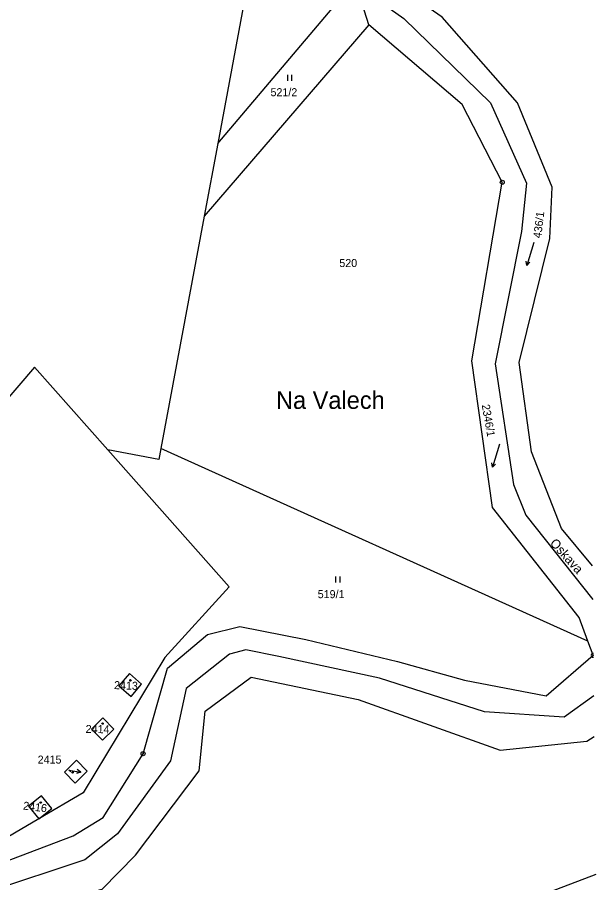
# Model space of a CAD drawing. Extents: x -555757 to -553364, y -1100723 to -1096439.
# Drawn here: x -553764.6 to -553620.1, y -1099734.7 to -1099518.5 of the extents above; entities that cross this region are included whole.
import ezdxf

# ---------------------------------------------------------------- set-up
doc = ezdxf.new("R2010")
doc.units = 0
for name, color, linetype in [('00_NÁVRH - 0.35 mm', 7, 'Continuous'), ('BUDOVY', 7, 'Continuous'), ('C$SLO$PARCELY', 7, 'Continuous'), ('HRANICE$PARCELY', 7, 'Continuous'), ('HRANICE_PARCEL', 7, 'Continuous'), ('PLOTY', 7, 'Continuous'), ('SLOUPY', 7, 'Continuous'), ('VSTUP', 7, 'Continuous'), ('ZNA$KY$KULTUR', 7, 'Continuous')]:
    doc.layers.add(name, color=color, linetype=linetype)

# ---------------------------------------------------------------- blocks, each defined once
blk = doc.blocks.new('8$02')
at = {"layer": 'ZNA$KY$KULTUR'}
for p, q in [((0.864, 2.855), (-0.89, -2.882)), ((-0.89, -2.882), (-1.083, -1.802)), ((-0.89, -2.882), (-0.125, -2.095))]:
    blk.add_line(p, q, dxfattribs=at)
blk = doc.blocks.new('4$02')
at = {"layer": 'SLOUPY'}
blk.add_circle((0, 0), 0.175, dxfattribs=at)
blk = doc.blocks.new('1029')
at = {"layer": 'PLOTY'}
for p, q in [((0, 0), (2.964, -0.468)), ((2.964, -0.468), (2.052, 0.182)), ((2.964, -0.468), (1.897, -0.807))]:
    blk.add_line(p, q, dxfattribs=at)
blk = doc.blocks.new('3$06')
at = {"layer": 'SLOUPY'}
for p, q in [((-0.517, 0.235), (-0.517, 1.735)), ((0.517, 0.235), (0.517, 1.735))]:
    blk.add_line(p, q, dxfattribs=at)
blk = doc.blocks.new('1$05')
at = {"layer": 'SLOUPY'}
for radius in [0.5, 0.032]:
    blk.add_circle((0, 0), radius, dxfattribs=at)

msp = doc.modelspace()

# ---------------------------------------------------------------- linework, layer by layer
at = {"layer": '00_NÁVRH - 0.35 mm'}
msp.add_open_spline([(-553819.59, -1099648.16), (-553819.4, -1099646.98), (-553818.56, -1099642.68), (-553816.68, -1099632.95), (-553812.02, -1099604.96), (-553809.79, -1099592.42), (-553806.53, -1099573.82), (-553806.2, -1099571.41), (-553804.77, -1099565.39), (-553798.08, -1099537.61), (-553796.19, -1099528.87), (-553794.16, -1099518.96), (-553793.97, -1099518.03), (-553793.87, -1099517.09), (-553793.75, -1099515.21), (-553792.36, -1099501.3), (-553791.83, -1099495.69), (-553791.31, -1099490.99), (-553790.46, -1099486.24), (-553789.17, -1099479.65), (-553786.51, -1099466.71), (-553785.83, -1099463.11), (-553785.36, -1099460.98), (-553785.14, -1099459.44), (-553784.73, -1099457.36), (-553781.96, -1099447.34), (-553777.86, -1099430.86), (-553775.87, -1099421.47), (-553773.63, -1099411.99), (-553771.23, -1099402.7), (-553769.36, -1099395.48), (-553768.64, -1099392.98), (-553768.18, -1099390.94), (-553766.28, -1099385.06), (-553765.16, -1099381.85), (-553762.51, -1099373.89), (-553760.31, -1099367.21), (-553759.89, -1099365.84), (-553759.44, -1099362.93), (-553758.89, -1099359.25), (-553758.81, -1099358.33), (-553758.87, -1099357.66), (-553759.04, -1099356.6), (-553759.19, -1099356.07), (-553760.05, -1099353.69), (-553760.55, -1099352.56), (-553766.32, -1099340.88), (-553766.88, -1099339.66), (-553767.75, -1099337.24), (-553769.45, -1099332.64), (-553770.89, -1099328.75), (-553771.54, -1099327.26), (-553772.2, -1099326.35), (-553775.73, -1099321.61), (-553781.22, -1099315.05), (-553785.27, -1099310.83), (-553785.54, -1099310.54), (-553785.73, -1099310.27), (-553786.37, -1099309.39), (-553819.5, -1099647.57), (-553786.04, -1099309.83)], degree=3, dxfattribs=at)
at = {"layer": 'HRANICE$PARCELY'}
for p, q in [((-553676.74, -1099520.32), (-553680.4, -1099508.77)), ((-553714.51, -1099549.98), (-553683.18, -1099513.03)), ((-553708.15, -1099515.9), (-553714.51, -1099549.98)), ((-553676.74, -1099520.32), (-553717.88, -1099568.1)), ((-553714.51, -1099549.98), (-553717.88, -1099568.1)), ((-553717.88, -1099568.1), (-553728.71, -1099626.16)), ((-553729.22, -1099628.91), (-553741.95, -1099626.54)), ((-553728.71, -1099626.16), (-553729.22, -1099628.91)), ((-553622, -1099674.28), (-553728.71, -1099626.16)), ((-553620.06, -1099732.58), (-553674.71, -1099753.42))]:
    msp.add_line(p, q, dxfattribs=at)
for points in [[(-553620.89, -1099655.48), (-553628.63, -1099646.14), (-553636.12, -1099627.02), (-553639.15, -1099604.73), (-553631.51, -1099573.7), (-553630.95, -1099560.93), (-553639.63, -1099539.86), (-553658.46, -1099518.43), (-553668.42, -1099511.39), (-553668.51, -1099470.76), (-553654.07, -1099454.92), (-553633.67, -1099447), (-553623.15, -1099447.06)], [(-553622, -1099674.28), (-553624.18, -1099668.44), (-553645.83, -1099640.94), (-553650.97, -1099604.28), (-553643.39, -1099559.66), (-553653.45, -1099540.26), (-553676.74, -1099520.32)], [(-553741.95, -1099626.54), (-553760.26, -1099605.89), (-553773.14, -1099620.73)], [(-553741.95, -1099626.54), (-553711.63, -1099660.73), (-553727.7, -1099678.41), (-553748.14, -1099712.19), (-553759.2, -1099718.67), (-553776.11, -1099728.59)], [(-553772.86, -1099731.35), (-553750.62, -1099722.98), (-553743.14, -1099718.36), (-553733.17, -1099702.43), (-553727.09, -1099681.04), (-553717.04, -1099672.62), (-553708.98, -1099670.62), (-553692.52, -1099673.88), (-553669.59, -1099679.36), (-553652.81, -1099684.04), (-553632.42, -1099688), (-553620.66, -1099677.84), (-553622, -1099674.28)], [(-553739.2, -1099685.47), (-553736.14, -1099688.11), (-553733.55, -1099685.03), (-553736.58, -1099682.42), (-553739.2, -1099685.47)], [(-553803.28, -1099822.6), (-553800.12, -1099797.62), (-553791.55, -1099769.92), (-553769.18, -1099743.04), (-553743.39, -1099736.29), (-553735.05, -1099727.74), (-553719.16, -1099706.71), (-553717.63, -1099691.83), (-553706.15, -1099683.31), (-553679.42, -1099688.88), (-553643.93, -1099701.57), (-553622.25, -1099699.32), (-553620.43, -1099698.1)], [(-553746.01, -1099696.28), (-553743.27, -1099699.03), (-553740.46, -1099696.26), (-553743.22, -1099693.49), (-553746.01, -1099696.28)], [(-553749.77, -1099704.03), (-553752.83, -1099707), (-553750.16, -1099709.76), (-553747.12, -1099706.78), (-553749.77, -1099704.03)], [(-553759.2, -1099718.67), (-553755.98, -1099716.12), (-553758.57, -1099712.93), (-553761.76, -1099715.51), (-553759.2, -1099718.67)]]:
    msp.add_lwpolyline(points, dxfattribs=at)
at = {"layer": 'HRANICE_PARCEL'}
for points in [[(-553623.22, -1099440.62), (-553637.4, -1099440.59), (-553654.89, -1099447.65), (-553661.99, -1099453.57), (-553674.34, -1099467.66), (-553675.45, -1099472.16), (-553673.92, -1099502.92), (-553674.7, -1099509.57), (-553672.87, -1099515.35), (-553668, -1099518.73), (-553646.32, -1099539.83), (-553637.37, -1099559.91), (-553638.63, -1099571.96), (-553645.19, -1099605.07), (-553640.58, -1099635.18), (-553637.5, -1099642.82), (-553620.8, -1099663.93)], [(-553623.22, -1099440.62), (-553637.4, -1099440.59), (-553654.89, -1099447.65), (-553661.99, -1099453.57), (-553674.34, -1099467.66), (-553675.45, -1099472.16), (-553673.92, -1099502.92), (-553674.7, -1099509.57), (-553672.87, -1099515.35), (-553668, -1099518.73), (-553646.32, -1099539.83), (-553637.37, -1099559.91), (-553638.63, -1099571.96), (-553645.19, -1099605.07), (-553640.58, -1099635.18), (-553637.5, -1099642.82), (-553620.8, -1099663.93)], [(-553620.54, -1099687.95), (-553627.97, -1099693.34), (-553647.84, -1099691.97), (-553674.12, -1099683.54), (-553699.27, -1099678.15), (-553707.5, -1099676.52), (-553711.54, -1099677.53), (-553722.43, -1099686.1), (-553726.32, -1099704.19), (-553739.54, -1099722.43), (-553747.73, -1099728.95), (-553771.83, -1099736.9), (-553787.11, -1099752.56), (-553796.41, -1099764.53), (-553805.28, -1099789.79), (-553805.39, -1099798.72), (-553806.07, -1099808.49), (-553810.02, -1099814.54), (-553812.43, -1099822.35)], [(-553620.54, -1099687.95), (-553627.97, -1099693.34), (-553647.84, -1099691.97), (-553674.12, -1099683.54), (-553699.27, -1099678.15), (-553707.5, -1099676.52), (-553711.54, -1099677.53), (-553722.43, -1099686.1), (-553726.32, -1099704.19), (-553739.54, -1099722.43), (-553747.73, -1099728.95), (-553771.83, -1099736.9), (-553787.11, -1099752.56), (-553796.41, -1099764.53), (-553805.28, -1099789.79), (-553805.39, -1099798.72), (-553806.07, -1099808.49), (-553810.02, -1099814.54), (-553812.43, -1099822.35)]]:
    msp.add_lwpolyline(points, dxfattribs=at)
at = {"layer": 'PLOTY'}
msp.add_line((-553751.22, -1099706.98), (-553751.68, -1099706.55), dxfattribs=at)
at = {"layer": 'VSTUP'}
for radius, start, end in [(0.5, 89.6831, 271.5549), (0.0303, 74.9825, 286.2556)]:
    msp.add_arc((-553620.66, -1099677.84), radius, start, end, dxfattribs=at)

# ---------------------------------------------------------------- block references
at = {"layer": 'BUDOVY'}
for p in [(-553736.3, -1099684.1), (-553743.27, -1099694.9), (-553750.78, -1099707.11), (-553758.74, -1099714.65)]:
    msp.add_blockref('4$02', p, dxfattribs=at)
at = {"layer": 'PLOTY'}
msp.add_blockref('1029', (-553751.68, -1099706.55), dxfattribs=at)
at = {"layer": 'VSTUP'}
for p in [(-553643.39, -1099559.66), (-553733.17, -1099702.43)]:
    msp.add_blockref('1$05', p, dxfattribs=at)
at = {"layer": 'ZNA$KY$KULTUR'}
for name, p in [('3$06', (-553696.47, -1099534.6)), ('8$02', (-553636.36, -1099577.55)), ('8$02', (-553644.97, -1099627.97)), ('3$06', (-553684.46, -1099659.86))]:
    msp.add_blockref(name, p, dxfattribs=at)

# ---------------------------------------------------------------- texts
at = {"layer": 'C$SLO$PARCELY'}
for s, p in [('521/2', (-553701.32, -1099538.17)), ('520', (-553684.12, -1099580.85)), ('519/1', (-553689.52, -1099663.57)), ('2415', (-553759.5, -1099704.9))]:
    msp.add_text(s, height=2, dxfattribs=at).set_placement(p)
for s, rotation, p in [('436/1', 83, (-553633.7, -1099573.74)), ('2346/1', 280, (-553648.54, -1099615.32)), ('2413', 358, (-553740.44, -1099686.28)), ('2414', 359, (-553747.52, -1099697.23)), ('2416', 353, (-553763.21, -1099716.36))]:
    msp.add_text(s, height=2, rotation=rotation, dxfattribs=at).set_placement(p)
at = {"layer": 'PLOTY'}
msp.add_text('Na Valech', height=4.4, dxfattribs=at).set_placement((-553699.93, -1099616.29))
msp.add_text('Oskava', height=2.3, rotation=312, dxfattribs=at).set_placement((-553631.65, -1099649.94))

doc.saveas('drawing.dxf')
